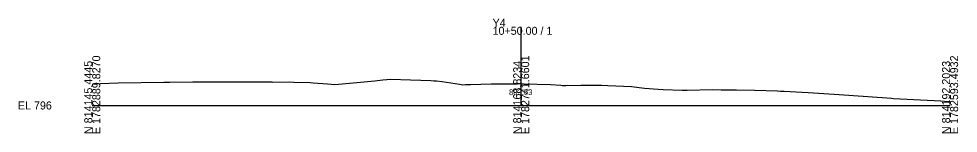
# Model space of a CAD drawing. Extents: x -26 to 3903, y -10 to 9562.
# Drawn here: x -25.7 to 302.8, y 490.3 to 530.3 of the extents above; entities that cross this region are included whole.
import ezdxf

# ---------------------------------------------------------------- set-up
doc = ezdxf.new("R2010")
doc.units = 0
for name, color, linetype in [('Exist Cross Section Cell', 7, 'Continuous'), ('Exist XS Center Line Elevation Label', 7, 'Continuous'), ('Exist XS Ground Line', 7, 'Continuous')]:
    doc.layers.add(name, color=color, linetype=linetype)

msp = doc.modelspace()

# ---------------------------------------------------------------- linework, layer by layer
at = {"layer": 'Exist Cross Section Cell'}
for p, q in [((150, 500), (150, 527.51)), ((0, 500), (150, 500)), ((150, 500), (300, 500))]:
    msp.add_line(p, q, dxfattribs=at)
at = {"layer": 'Exist XS Ground Line'}
for p, q in [((0, 507.51), (2.9, 507.65)), ((2.9, 507.65), (9.1, 507.91)), ((9.1, 507.91), (24.99, 508.11)), ((24.99, 508.11), (27.17, 508.14)), ((27.17, 508.14), (35.17, 508.23)), ((35.17, 508.23), (45.36, 508.26)), ((45.36, 508.26), (53.53, 508.28)), ((53.53, 508.28), (58.2, 508.3)), ((58.2, 508.3), (62.92, 508.3)), ((62.92, 508.3), (62.94, 508.15)), ((62.94, 508.15), (69.14, 508.23)), ((69.14, 508.23), (70.44, 508.2)), ((70.44, 508.2), (76.21, 507.98)), ((76.21, 507.98), (77.31, 507.87)), ((77.31, 507.87), (82.28, 507.53)), ((82.28, 507.53), (84.87, 507.35)), ((84.87, 507.35), (92.56, 508.02)), ((92.56, 508.02), (98.83, 508.65)), ((98.83, 508.65), (101.6, 508.96)), ((101.6, 508.96), (104.37, 509.17)), ((104.37, 509.17), (111.29, 509)), ((111.29, 509), (114.96, 508.88)), ((114.96, 508.88), (118.36, 508.71)), ((118.36, 508.71), (119.45, 508.65)), ((119.45, 508.65), (120.34, 508.59)), ((120.34, 508.59), (122.34, 508.42)), ((122.34, 508.42), (128.43, 507.41)), ((128.43, 507.41), (129.6, 507.24)), ((129.6, 507.24), (130.57, 507.28)), ((130.57, 507.28), (132.26, 507.34)), ((132.26, 507.34), (139.55, 507.61)), ((139.55, 507.61), (147.28, 507.62)), ((147.28, 507.62), (148.69, 507.62)), ((148.69, 507.62), (150.02, 507.63)), ((150.02, 507.63), (151.09, 507.6)), ((151.09, 507.6), (160.25, 507.38)), ((160.25, 507.38), (163.88, 507.08)), ((163.88, 507.08), (164.45, 507.01)), ((164.45, 507.01), (165.65, 507.04)), ((165.65, 507.04), (170.87, 507.06)), ((170.87, 507.06), (175.35, 507.1)), ((175.35, 507.1), (178.08, 507.11)), ((178.08, 507.11), (180.3, 507.01)), ((180.3, 507.01), (188.61, 506.6)), ((188.61, 506.6), (193.13, 506.02)), ((193.13, 506.02), (197.87, 505.7)), ((197.87, 505.7), (199.65, 505.57)), ((199.65, 505.57), (206.36, 505.36)), ((206.36, 505.36), (207.71, 505.33)), ((207.71, 505.33), (208.1, 505.34)), ((208.1, 505.34), (216.76, 505.57)), ((216.76, 505.57), (219.96, 505.49)), ((219.96, 505.49), (225.29, 505.45)), ((225.29, 505.45), (231.62, 505.33)), ((231.62, 505.33), (239.6, 505.07)), ((239.6, 505.07), (240.72, 505.02)), ((240.72, 505.02), (241.92, 504.96)), ((241.92, 504.96), (250.37, 504.49)), ((250.37, 504.49), (259.44, 503.93)), ((259.44, 503.93), (264.55, 503.62)), ((264.55, 503.62), (279.48, 502.5)), ((279.48, 502.5), (280.24, 502.46)), ((280.24, 502.46), (296.8, 501.59)), ((296.8, 501.59), (298, 501.5)), ((298, 501.5), (300, 501.37))]:
    msp.add_line(p, q, dxfattribs=at)

# ---------------------------------------------------------------- texts
at = {"layer": 'Exist Cross Section Cell'}
for s, p in [('Y4', (140, 527.51)), ('10+50.00 / 1', (140, 524.71)), ('EL 796', (-26, 498.6))]:
    msp.add_text(s, height=2.8, dxfattribs=at).set_placement(p)
for s, p in [('E 1782889.8270', (2.8, 490)), ('E 1782741.6601', (152.8, 490)), ('E 1782593.4932', (302.8, 490)), ('N 814145.4445', (0, 490)), ('N 814168.8234', (150, 490)), ('N 814192.2023', (300, 490))]:
    msp.add_text(s, height=2.8, rotation=90, dxfattribs=at).set_placement(p)
at = {"layer": 'Exist XS Center Line Elevation Label'}
msp.add_text('803.63', height=2, dxfattribs=at).set_placement((145.75, 503.63))

doc.saveas('drawing.dxf')
